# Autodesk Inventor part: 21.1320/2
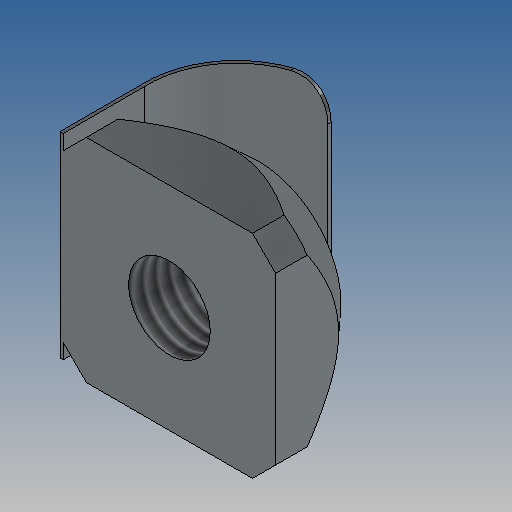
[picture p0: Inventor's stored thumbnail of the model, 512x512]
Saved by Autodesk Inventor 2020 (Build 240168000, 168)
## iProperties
Created: 2006-12
Part Number: 21.1320/2
Document SubType Name: Modeling
Designer: Andy Moles
Material: Steel, Mild
Density: 7.85 g/cm^3
Mass: 5.5713 g
Surface Area: 8.43697 cm^2
Volume: 0.70972 cm^3
Description: M5 SQUARE NUT POS FXG
Vendor: S
Appearance: Zinc
Author: Andy Moles
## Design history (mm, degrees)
sketch "Sketch2"
  geometry: L1 (-5.086, -6.5)-(5.086, -6.5); L2 (6.5, -5.086)-(6.5, 5.086); L3 (5.086, 6.5)-(-5.086, 6.5); L4 (-6.5, 5.086)-(-6.5, -5.086); L5 (-6.5, 6.5)-(6.5, -6.5); L6 (5.086, 6.5)-(6.5, 5.086); L7 (0, -6.5)-(0, 6.5); L8 (-6.5, 0)-(6.5, 0); L9 (-5.086, 6.5)-(-6.5, 5.086); L10 (-5.086, -6.5)-(-6.5, -5.086); L11 (5.086, -6.5)-(6.5, -5.086); C1 r 2.5 at (0, 0); 2 further points
  constraints: 22 end point, 6 symmetric about line, 4 parallel, 3 midpoint, 2 coincident, 2 perpendicular, 1 centre point, 1 horizontal
  dimensions: "THREAD" = 5 diameter of C1; "d3" = 45 deg angle of L3 L6 (derived); "d4" = 2 distance of L3.start L2.end
extrude "Extrusion1" new body sketch "Sketch2" distance "d5" = 5.5; taper "d6" = 0 deg
workplane "Work Plane1"
sketch "Sketch4"
  geometry: L1 (10.692, 0)-(5.692, 0) reference; L2 (8.192, 0)-(13.192, 0); L3 (16.385, 5.5)-(16.385, 3.5); L4 (13.192, 0)-(16.797, 3.952); L5 (13.192, 0)-(16.385, 0); L6 (16.385, 3.5)-(16.385, 0); L7 (16.797, 3.952)-(16.797, -0.412); L8 (16.797, -0.412)-(13.192, -0.412); L9 (13.192, -0.412)-(13.192, 0); L10 (8.192, 5.5)-(8.192, 0); L11 (16.385, 5.5)-(16.385, 0) reference; L12 (16.385, 3.5)-(17.502, 3.5); L13 (9.192, 5.5)-(16.385, 5.5) reference
  constraints: 20 end point, 6 perpendicular, 1 collinear, 1 midpoint, 1 parallel, 1 point on line
  dimensions: "d10" = 5 distance of L2.start L2.end; "d15" = 2 distance between parallel lines of L12 L13
revolve "Revolution1" sketch "Sketch4" stored, may be unused: angle "d12" = 90 deg
thread "Thread1" dims "d13" = 10, "d14" = 0
sketch "Sketch6"
  geometry: L1 (6.5, 0)-(6.5, 6.006); L2 (6.5, 0)-(6.5, -5); L3 (6.5, 0)-(6.7, 0); L4 (6.7, 0)-(6.7, -5); L5 (0.9, -10.6)-(0.9, -10.8); L6 (6.5, 0)-(6.5, -1.933); L7 (-5.086, 0)-(5.086, 0); A1 r 5.374 centre (1.131, -5.231) between (0.9, -10.6) and (6.5, -5); A2 r 5.574 centre (1.131, -5.231) between (0.9, -10.8) and (6.7, -5); 3 further points
  constraints: 14 end point, 4 point on circle, 3 collinear, 2 centre point, 2 parallel, 2 perpendicular, 1 coincident
  dimensions: "d21" = 5 distance of L1.start L2.end; "d22" = 0.2 distance of L1.start L3.end; "d23" = 0.2 distance of L5.start L5.end; "d24" = 10.8 distance from line of L5.end L3; "d25" = 5.37434 radius of A1
extrude "Extrusion3" join sketch "Sketch6" stored distance "d26" = 12; taper "d27" = 0 deg
fillet "Fillet2" dims "d28" = 2
fillet "Fillet3" dims "d29" = 2
body "Solid1"
